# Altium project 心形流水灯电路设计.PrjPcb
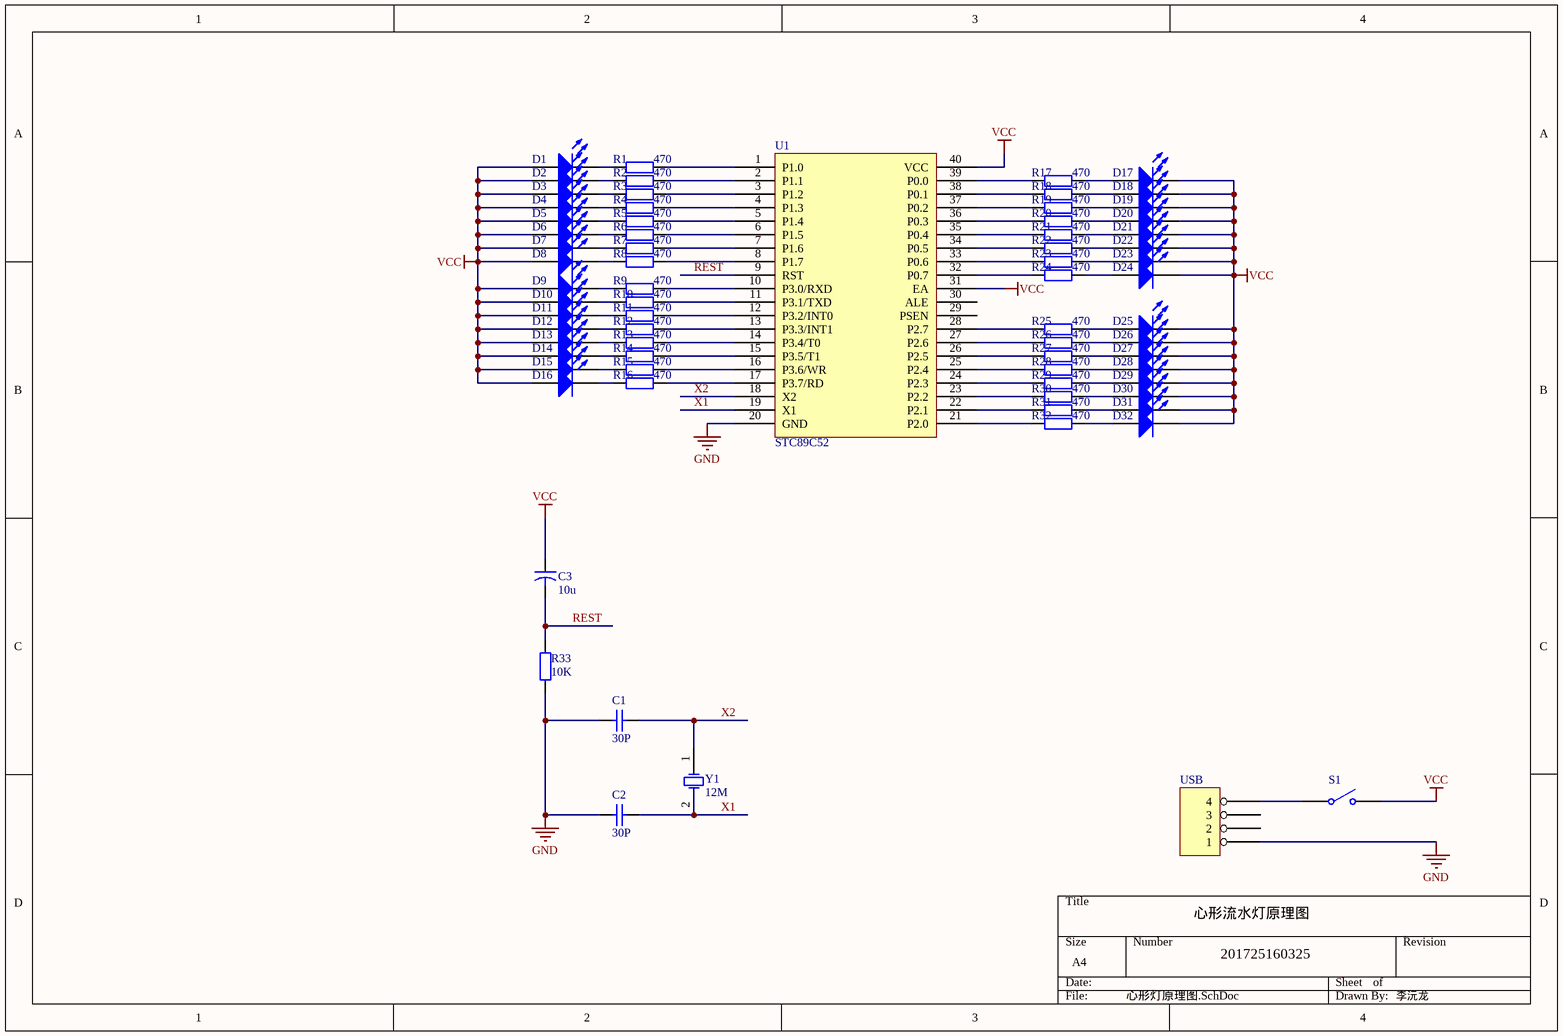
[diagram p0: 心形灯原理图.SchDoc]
1 sheet, 72 parts. Net scope: global (net labels, ports and power ports of the same name join across sheets).
Board file: 心形灯PCB图.PcbDoc

## Sheet 心形灯原理图.SchDoc
size A4

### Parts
C1  30P  [RAD-0.3]
C2  30P  [RAD-0.3]
C3  10u  [CAPR5-4X5]
D1  (no value)  [LED-0]
D2  (no value)  [LED-0]
D3  (no value)  [LED-0]
D4  (no value)  [LED-0]
D5  (no value)  [LED-0]
D6  (no value)  [LED-0]
D7  (no value)  [LED-0]
D8  (no value)  [LED-0]
D9  (no value)  [LED-0]
D10  (no value)  [LED-0]
D11  (no value)  [LED-0]
D12  (no value)  [LED-0]
D13  (no value)  [LED-0]
D14  (no value)  [LED-0]
D15  (no value)  [LED-0]
D16  (no value)  [LED-0]
D17  (no value)  [LED-0]
D18  (no value)  [LED-0]
D19  (no value)  [LED-0]
D20  (no value)  [LED-0]
D21  (no value)  [LED-0]
D22  (no value)  [LED-0]
D23  (no value)  [LED-0]
D24  (no value)  [LED-0]
D25  (no value)  [LED-0]
D26  (no value)  [LED-0]
D27  (no value)  [LED-0]
D28  (no value)  [LED-0]
D29  (no value)  [LED-0]
D30  (no value)  [LED-0]
D31  (no value)  [LED-0]
D32  (no value)  [LED-0]
R1  470  [AXIAL-0.4]
R2  470  [AXIAL-0.4]
R3  470  [AXIAL-0.4]
R4  470  [AXIAL-0.4]
R5  470  [AXIAL-0.4]
R6  470  [AXIAL-0.4]
R7  470  [AXIAL-0.4]
R8  470  [AXIAL-0.4]
R9  470  [AXIAL-0.4]
R10  470  [AXIAL-0.4]
R11  470  [AXIAL-0.4]
R12  470  [AXIAL-0.4]
R13  470  [AXIAL-0.4]
R14  470  [AXIAL-0.4]
R15  470  [AXIAL-0.4]
R16  470  [AXIAL-0.4]
R17  470  [AXIAL-0.4]
R18  470  [AXIAL-0.4]
R19  470  [AXIAL-0.4]
R20  470  [AXIAL-0.4]
R21  470  [AXIAL-0.4]
R22  470  [AXIAL-0.4]
R23  470  [AXIAL-0.4]
R24  470  [AXIAL-0.4]
R25  470  [AXIAL-0.4]
R26  470  [AXIAL-0.4]
R27  470  [AXIAL-0.4]
R28  470  [AXIAL-0.4]
R29  470  [AXIAL-0.4]
R30  470  [AXIAL-0.4]
R31  470  [AXIAL-0.4]
R32  470  [AXIAL-0.4]
R33  10K  [AXIAL-0.4]
S1  (no value)  [SPST-2]
U1  STC89C52
USB  (no value)
Y1  12M  [R38]

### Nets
GND: C1.1 C2.1 R33.1 U1.20(GND) USB.?1(1)
VCC: C3.1 D1.1(A) D2.1(A) D3.1(A) D4.1(A) D5.1(A) D6.1(A) D7.1(A) D8.1(A) D9.1(A) D10.1(A) D11.1(A) D12.1(A) D13.1(A) D14.1(A) D15.1(A) D16.1(A) D17.2(K) D18.2(K) D19.2(K) D20.2(K) D21.2(K) D22.2(K) D23.2(K) D24.2(K) D25.2(K) D26.2(K) D27.2(K) D28.2(K) D29.2(K) D30.2(K) D31.2(K) D32.2(K) S1.2(NO) U1.31(EA) U1.40(VCC)
REST: C3.2 R33.2 U1.9(RST)
X1: C2.2 U1.19(X1) Y1.2(OSC2)
X2: C1.2 U1.18(X2) Y1.1(OSC1)
NetD1_2: D1.2(K) R1.1
NetD2_2: D2.2(K) R2.1
NetD3_2: D3.2(K) R3.1
NetD4_2: D4.2(K) R4.1
NetD5_2: D5.2(K) R5.1
NetD6_2: D6.2(K) R6.1
NetD7_2: D7.2(K) R7.1
NetD8_2: D8.2(K) R8.1
NetD9_2: D9.2(K) R9.1
NetD10_2: D10.2(K) R10.1
NetD11_2: D11.2(K) R11.1
NetD12_2: D12.2(K) R12.1
NetD13_2: D13.2(K) R13.1
NetD14_2: D14.2(K) R14.1
NetD15_2: D15.2(K) R15.1
NetD16_2: D16.2(K) R16.1
NetD17_1: D17.1(A) R17.2
NetD18_1: D18.1(A) R18.2
NetD19_1: D19.1(A) R19.2
NetD20_1: D20.1(A) R20.2
NetD21_1: D21.1(A) R21.2
NetD22_1: D22.1(A) R22.2
NetD23_1: D23.1(A) R23.2
NetD24_1: D24.1(A) R24.2
NetD25_1: D25.1(A) R25.2
NetD26_1: D26.1(A) R26.2
NetD27_1: D27.1(A) R27.2
NetD28_1: D28.1(A) R28.2
NetD29_1: D29.1(A) R29.2
NetD30_1: D30.1(A) R30.2
NetD31_1: D31.1(A) R31.2
NetD32_1: D32.1(A) R32.2
NetR1_2: R1.2 U1.1(P1.0)
NetR2_2: R2.2 U1.2(P1.1)
NetR3_2: R3.2 U1.3(P1.2)
NetR4_2: R4.2 U1.4(P1.3)
NetR5_2: R5.2 U1.5(P1.4)
NetR6_2: R6.2 U1.6(P1.5)
NetR7_2: R7.2 U1.7(P1.6)
NetR8_2: R8.2 U1.8(P1.7)
NetR9_2: R9.2 U1.10(P3.0/RXD)
NetR10_2: R10.2 U1.11(P3.1/TXD)
NetR11_2: R11.2 U1.12(P3.2/INT0)
NetR12_2: R12.2 U1.13(P3.3/INT1)
NetR13_2: R13.2 U1.14(P3.4/T0)
NetR14_2: R14.2 U1.15(P3.5/T1)
NetR15_2: R15.2 U1.16(P3.6/WR)
NetR16_2: R16.2 U1.17(P3.7/RD)
NetR17_1: R17.1 U1.39(P0.0)
NetR18_1: R18.1 U1.38(P0.1)
NetR19_1: R19.1 U1.37(P0.2)
NetR20_1: R20.1 U1.36(P0.3)
NetR21_1: R21.1 U1.35(P0.4)
NetR22_1: R22.1 U1.34(P0.5)
NetR23_1: R23.1 U1.33(P0.6)
NetR24_1: R24.1 U1.32(P0.7)
NetR25_1: R25.1 U1.28(P2.7)
NetR26_1: R26.1 U1.27(P2.6)
NetR27_1: R27.1 U1.26(P2.5)
NetR28_1: R28.1 U1.25(P2.4)
NetR29_1: R29.1 U1.24(P2.3)
NetR30_1: R30.1 U1.23(P2.2)
NetR31_1: R31.1 U1.22(P2.1)
NetR32_1: R32.1 U1.21(P2.0)
NetS1_1: S1.1(COMMON) USB.?4(4)

Not connected (* = marked no-connect by the designer): U1 29(PSEN) 30(ALE); USB ?2(2) ?3(3)

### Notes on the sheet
- 心形流水灯原理图
- 201725160325
- 李沅龙

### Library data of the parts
C1 C2 = Cap: Capacitor; Value: 100pF
C3 = Cap2: Capacitor; Value: 100pF
D1-D32 = LED0: Typical INFRARED GaAs LED
R1-R33 = Res2: Resistor; Value: 1K
S1 = SW-SPST: Single-Pole, Single-Throw Switch
U1 = Component_1
USB = USB
Y1 = XTAL: Crystal Oscillator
